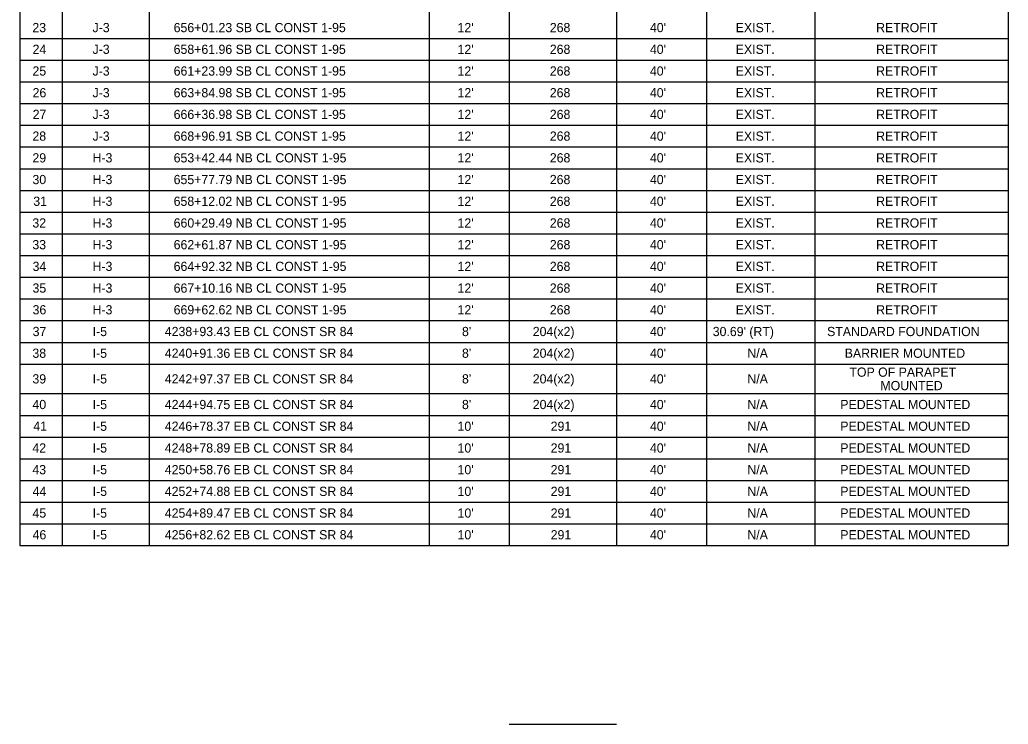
# Model space of a CAD drawing. Extents: x -838.2 to -802.1, y -2200.5 to -2187.7.
# Drawn here: x -838.21 to -830.69, y -2200.46 to -2195.1 of the extents above; entities that cross this region are included whole.
import ezdxf

# ---------------------------------------------------------------- set-up
doc = ezdxf.new("R2010")
doc.units = 0
for name, color, linetype in [('SumBoxBorder_dp', 7, 'Continuous'), ('SumBoxLines_dp', 7, 'Continuous'), ('SumBoxLinesMin_dp', 7, 'Continuous'), ('TextLabel', 7, 'Continuous')]:
    doc.layers.add(name, color=color, linetype=linetype)

msp = doc.modelspace()

# ---------------------------------------------------------------- linework, layer by layer
at = {"layer": 'SumBoxBorder_dp'}
for p, q in [((-838.2083, -2189.7484), (-838.2083, -2199.1009)), ((-830.6933, -2189.7484), (-830.6933, -2199.1009)), ((-830.6933, -2189.7484), (-830.6933, -2199.1009)), ((-838.2083, -2199.1009), (-830.6933, -2199.1009)), ((-837.2258, -2199.1009), (-835.0958, -2199.1009))]:
    msp.add_line(p, q, dxfattribs=at)
at = {"layer": 'SumBoxLines_dp'}
for p, q in [((-837.8858, -2190.0784), (-837.8858, -2199.1009)), ((-837.8858, -2190.0784), (-837.8858, -2199.1009)), ((-837.2258, -2190.0784), (-837.2258, -2199.1009)), ((-837.2258, -2190.0784), (-837.2258, -2199.1009)), ((-835.0958, -2190.0784), (-835.0958, -2197.0609)), ((-835.0958, -2190.0784), (-835.0958, -2199.1009)), ((-834.4883, -2190.0784), (-834.4883, -2199.1009)), ((-834.4883, -2190.0784), (-834.4883, -2199.1009)), ((-833.6708, -2190.0784), (-833.6708, -2199.1009)), ((-833.6708, -2190.0784), (-833.6708, -2199.1009)), ((-832.9883, -2190.0784), (-832.9883, -2199.1009)), ((-832.9883, -2190.0784), (-832.9883, -2199.1009)), ((-832.1633, -2190.0784), (-832.1633, -2199.1009)), ((-832.1633, -2190.0784), (-832.1633, -2199.1009)), ((-835.0958, -2197.2259), (-835.0958, -2199.1009))]:
    msp.add_line(p, q, dxfattribs=at)
at = {"layer": 'SumBoxLinesMin_dp'}
for p, q in [((-838.2083, -2195.2459), (-830.6933, -2195.2459)), ((-838.2083, -2195.2459), (-830.6933, -2195.2459)), ((-838.2083, -2195.4109), (-830.6933, -2195.4109)), ((-838.2083, -2195.4109), (-830.6933, -2195.4109)), ((-838.2083, -2195.5759), (-830.6933, -2195.5759)), ((-838.2083, -2195.5759), (-830.6933, -2195.5759)), ((-838.2083, -2195.7409), (-830.6933, -2195.7409)), ((-838.2083, -2195.7409), (-830.6933, -2195.7409)), ((-838.2083, -2195.9059), (-830.6933, -2195.9059)), ((-838.2083, -2195.9059), (-830.6933, -2195.9059)), ((-838.2083, -2196.0709), (-830.6933, -2196.0709)), ((-838.2083, -2196.0709), (-830.6933, -2196.0709)), ((-838.2083, -2196.2359), (-830.6933, -2196.2359)), ((-838.2083, -2196.2359), (-830.6933, -2196.2359)), ((-838.2083, -2196.4009), (-830.6933, -2196.4009)), ((-838.2083, -2196.4009), (-830.6933, -2196.4009)), ((-838.2083, -2196.5659), (-830.6933, -2196.5659)), ((-838.2083, -2196.5659), (-830.6933, -2196.5659)), ((-838.2083, -2196.7309), (-830.6933, -2196.7309)), ((-838.2083, -2196.7309), (-830.6933, -2196.7309)), ((-838.2083, -2196.8959), (-830.6933, -2196.8959)), ((-838.2083, -2196.8959), (-830.6933, -2196.8959)), ((-838.2083, -2197.0609), (-830.6933, -2197.0609)), ((-838.2083, -2197.0609), (-830.6933, -2197.0609)), ((-838.2083, -2197.2259), (-837.2258, -2197.2259)), ((-838.2083, -2197.2259), (-830.6933, -2197.2259)), ((-835.0958, -2197.2259), (-830.6933, -2197.2259)), ((-838.2083, -2197.3909), (-830.6933, -2197.3909)), ((-838.2083, -2197.3909), (-830.6933, -2197.3909)), ((-838.2083, -2197.5559), (-830.6933, -2197.5559)), ((-838.2083, -2197.5559), (-830.6933, -2197.5559)), ((-838.2083, -2197.7209), (-830.6933, -2197.7209)), ((-838.2083, -2197.7209), (-830.6933, -2197.7209)), ((-838.2083, -2197.9459), (-830.6933, -2197.9459)), ((-838.2083, -2197.9459), (-830.6933, -2197.9459)), ((-838.2083, -2198.1109), (-830.6933, -2198.1109)), ((-838.2083, -2198.1109), (-830.6933, -2198.1109)), ((-838.2083, -2198.2759), (-830.6933, -2198.2759)), ((-838.2083, -2198.2759), (-830.6933, -2198.2759)), ((-838.2083, -2198.4409), (-830.6933, -2198.4409)), ((-838.2083, -2198.4409), (-830.6933, -2198.4409)), ((-838.2083, -2198.6059), (-830.6933, -2198.6059)), ((-838.2083, -2198.6059), (-830.6933, -2198.6059)), ((-838.2083, -2198.7709), (-830.6933, -2198.7709)), ((-838.2083, -2198.7709), (-830.6933, -2198.7709)), ((-838.2083, -2198.9359), (-837.2258, -2198.9359)), ((-838.2083, -2198.9359), (-830.6933, -2198.9359)), ((-835.0958, -2198.9359), (-830.6933, -2198.9359)), ((-837.8858, -2199.1009), (-837.2258, -2199.1009)), ((-835.0958, -2199.1009), (-834.4883, -2199.1009)), ((-832.1633, -2199.1009), (-830.6933, -2199.1009)), ((-834.4883, -2200.4584), (-833.6708, -2200.4584))]:
    msp.add_line(p, q, dxfattribs=at)

# ---------------------------------------------------------------- texts
at = {"layer": 'TextLabel'}
for s, p in [('23', (-838.1124, -2195.1984)), ('J-3', (-837.655, -2195.1984)), ('656+01.23 SB CL CONST 1-95', (-837.0383, -2195.1984)), ("12'", (-834.88, -2195.1984)), ('268', (-834.1785, -2195.1984)), ("40'", (-833.4175, -2195.1984)), ('EXIST.', (-832.7651, -2195.1984)), ('RETROFIT', (-831.6976, -2195.1984)), ('24', (-838.111, -2195.3634)), ('J-3', (-837.655, -2195.3634)), ('658+61.96 SB CL CONST 1-95', (-837.0383, -2195.3634)), ("12'", (-834.88, -2195.3634)), ('268', (-834.1785, -2195.3634)), ("40'", (-833.4175, -2195.3634)), ('EXIST.', (-832.7651, -2195.3634)), ('RETROFIT', (-831.6976, -2195.3634)), ('25', (-838.1115, -2195.5284)), ('J-3', (-837.655, -2195.5284)), ('661+23.99 SB CL CONST 1-95', (-837.0383, -2195.5284)), ("12'", (-834.88, -2195.5284)), ('268', (-834.1785, -2195.5284)), ("40'", (-833.4175, -2195.5284)), ('EXIST.', (-832.7651, -2195.5284)), ('RETROFIT', (-831.6976, -2195.5284)), ('26', (-838.111, -2195.6934)), ('J-3', (-837.655, -2195.6934)), ('663+84.98 SB CL CONST 1-95', (-837.0383, -2195.6934)), ("12'", (-834.88, -2195.6934)), ('268', (-834.1785, -2195.6934)), ("40'", (-833.4175, -2195.6934)), ('EXIST.', (-832.7651, -2195.6934)), ('RETROFIT', (-831.6976, -2195.6934)), ('27', (-838.1104, -2195.8584)), ('J-3', (-837.655, -2195.8584)), ('666+36.98 SB CL CONST 1-95', (-837.0383, -2195.8584)), ("12'", (-834.88, -2195.8584)), ('268', (-834.1785, -2195.8584)), ("40'", (-833.4175, -2195.8584)), ('EXIST.', (-832.7651, -2195.8584)), ('RETROFIT', (-831.6976, -2195.8584)), ('28', (-838.1121, -2196.0234)), ('J-3', (-837.655, -2196.0234)), ('668+96.91 SB CL CONST 1-95', (-837.0383, -2196.0234)), ("12'", (-834.88, -2196.0234)), ('268', (-834.1785, -2196.0234)), ("40'", (-833.4175, -2196.0234)), ('EXIST.', (-832.7651, -2196.0234)), ('RETROFIT', (-831.6976, -2196.0234)), ('29', (-838.112, -2196.1884)), ('H-3', (-837.655, -2196.1884)), ('653+42.44 NB CL CONST 1-95', (-837.0383, -2196.1884)), ("12'", (-834.88, -2196.1884)), ('268', (-834.1785, -2196.1884)), ("40'", (-833.4175, -2196.1884)), ('EXIST.', (-832.7651, -2196.1884)), ('RETROFIT', (-831.6976, -2196.1884)), ('30', (-838.1118, -2196.3534)), ('H-3', (-837.655, -2196.3534)), ('655+77.79 NB CL CONST 1-95', (-837.0383, -2196.3534)), ("12'", (-834.88, -2196.3534)), ('268', (-834.1785, -2196.3534)), ("40'", (-833.4175, -2196.3534)), ('EXIST.', (-832.7651, -2196.3534)), ('RETROFIT', (-831.6976, -2196.3534)), ('31', (-838.1056, -2196.5184)), ('H-3', (-837.655, -2196.5184)), ('658+12.02 NB CL CONST 1-95', (-837.0383, -2196.5184)), ("12'", (-834.88, -2196.5184)), ('268', (-834.1785, -2196.5184)), ("40'", (-833.4175, -2196.5184)), ('EXIST.', (-832.7651, -2196.5184)), ('RETROFIT', (-831.6976, -2196.5184)), ('32', (-838.1124, -2196.6834)), ('H-3', (-837.655, -2196.6834)), ('660+29.49 NB CL CONST 1-95', (-837.0383, -2196.6834)), ("12'", (-834.88, -2196.6834)), ('268', (-834.1785, -2196.6834)), ("40'", (-833.4175, -2196.6834)), ('EXIST.', (-832.7651, -2196.6834)), ('RETROFIT', (-831.6976, -2196.6834)), ('33', (-838.1124, -2196.8484)), ('H-3', (-837.655, -2196.8484)), ('662+61.87 NB CL CONST 1-95', (-837.0383, -2196.8484)), ("12'", (-834.88, -2196.8484)), ('268', (-834.1785, -2196.8484)), ("40'", (-833.4175, -2196.8484)), ('EXIST.', (-832.7651, -2196.8484)), ('RETROFIT', (-831.6976, -2196.8484)), ('34', (-838.111, -2197.0134)), ('H-3', (-837.655, -2197.0134)), ('664+92.32 NB CL CONST 1-95', (-837.0383, -2197.0134)), ("12'", (-834.88, -2197.0134)), ('268', (-834.1785, -2197.0134)), ("40'", (-833.4175, -2197.0134)), ('EXIST.', (-832.7651, -2197.0134)), ('RETROFIT', (-831.6976, -2197.0134)), ('35', (-838.1115, -2197.1784)), ('H-3', (-837.655, -2197.1784)), ('667+10.16 NB CL CONST 1-95', (-837.0383, -2197.1784)), ("12'", (-834.88, -2197.1784)), ('268', (-834.1785, -2197.1784)), ("40'", (-833.4175, -2197.1784)), ('EXIST.', (-832.7651, -2197.1784)), ('RETROFIT', (-831.6976, -2197.1784)), ('36', (-838.111, -2197.3434)), ('H-3', (-837.655, -2197.3434)), ('669+62.62 NB CL CONST 1-95', (-837.0383, -2197.3434)), ("12'", (-834.88, -2197.3434)), ('268', (-834.1785, -2197.3434)), ("40'", (-833.4175, -2197.3434)), ('EXIST.', (-832.7651, -2197.3434)), ('RETROFIT', (-831.6976, -2197.3434)), ('37', (-838.1104, -2197.5084)), ('I-5', (-837.6541, -2197.5084)), ('4238+93.43 EB CL CONST SR 84', (-837.1056, -2197.5084)), ("8'", (-834.8462, -2197.5084)), ('204(x2)', (-834.3081, -2197.5084)), ("40'", (-833.4175, -2197.5084)), ("30.69' (RT)", (-832.9398, -2197.5084)), ('STANDARD FOUNDATION', (-832.0707, -2197.5084)), ('38', (-838.1121, -2197.6734)), ('I-5', (-837.6541, -2197.6734)), ('4240+91.36 EB CL CONST SR 84', (-837.1056, -2197.6734)), ("8'", (-834.8462, -2197.6734)), ('204(x2)', (-834.3081, -2197.6734)), ("40'", (-833.4175, -2197.6734)), ('N/A', (-832.6765, -2197.6734)), ('BARRIER MOUNTED', (-831.9363, -2197.6734)), ('TOP OF PARAPET', (-831.9008, -2197.8174)), ('39', (-838.112, -2197.8684)), ('I-5', (-837.6541, -2197.8684)), ('4242+97.37 EB CL CONST SR 84', (-837.1056, -2197.8684)), ("8'", (-834.8462, -2197.8684)), ('204(x2)', (-834.3081, -2197.8684)), ("40'", (-833.4175, -2197.8684)), ('N/A', (-832.6765, -2197.8684)), ('MOUNTED', (-831.6652, -2197.9194)), ('40', (-838.1118, -2198.0634)), ('I-5', (-837.6541, -2198.0634)), ('4244+94.75 EB CL CONST SR 84', (-837.1056, -2198.0634)), ("8'", (-834.8462, -2198.0634)), ('204(x2)', (-834.3081, -2198.0634)), ("40'", (-833.4175, -2198.0634)), ('N/A', (-832.6765, -2198.0634)), ('PEDESTAL MOUNTED', (-831.9701, -2198.0634)), ('41', (-838.1056, -2198.2284)), ('I-5', (-837.6541, -2198.2284)), ('4246+78.37 EB CL CONST SR 84', (-837.1056, -2198.2284)), ("10'", (-834.88, -2198.2284)), ('291', (-834.172, -2198.2284)), ("40'", (-833.4175, -2198.2284)), ('N/A', (-832.6765, -2198.2284)), ('PEDESTAL MOUNTED', (-831.9701, -2198.2284)), ('42', (-838.1124, -2198.3934)), ('I-5', (-837.6541, -2198.3934)), ('4248+78.89 EB CL CONST SR 84', (-837.1056, -2198.3934)), ("10'", (-834.88, -2198.3934)), ('291', (-834.172, -2198.3934)), ("40'", (-833.4175, -2198.3934)), ('N/A', (-832.6765, -2198.3934)), ('PEDESTAL MOUNTED', (-831.9701, -2198.3934)), ('43', (-838.1124, -2198.5584)), ('I-5', (-837.6541, -2198.5584)), ('4250+58.76 EB CL CONST SR 84', (-837.1056, -2198.5584)), ("10'", (-834.88, -2198.5584)), ('291', (-834.172, -2198.5584)), ("40'", (-833.4175, -2198.5584)), ('N/A', (-832.6765, -2198.5584)), ('PEDESTAL MOUNTED', (-831.9701, -2198.5584)), ('44', (-838.111, -2198.7234)), ('I-5', (-837.6541, -2198.7234)), ('4252+74.88 EB CL CONST SR 84', (-837.1056, -2198.7234)), ("10'", (-834.88, -2198.7234)), ('291', (-834.172, -2198.7234)), ("40'", (-833.4175, -2198.7234)), ('N/A', (-832.6765, -2198.7234)), ('PEDESTAL MOUNTED', (-831.9701, -2198.7234)), ('45', (-838.1115, -2198.8884)), ('I-5', (-837.6541, -2198.8884)), ('4254+89.47 EB CL CONST SR 84', (-837.1056, -2198.8884)), ("10'", (-834.88, -2198.8884)), ('291', (-834.172, -2198.8884)), ("40'", (-833.4175, -2198.8884)), ('N/A', (-832.6765, -2198.8884)), ('PEDESTAL MOUNTED', (-831.9701, -2198.8884)), ('46', (-838.111, -2199.0534)), ('I-5', (-837.6541, -2199.0534)), ('4256+82.62 EB CL CONST SR 84', (-837.1056, -2199.0534)), ("10'", (-834.88, -2199.0534)), ('291', (-834.172, -2199.0534)), ("40'", (-833.4175, -2199.0534)), ('N/A', (-832.6765, -2199.0534)), ('PEDESTAL MOUNTED', (-831.9701, -2199.0534))]:
    msp.add_text(s, height=0.07, dxfattribs=at).set_placement(p)

doc.saveas('drawing.dxf')
